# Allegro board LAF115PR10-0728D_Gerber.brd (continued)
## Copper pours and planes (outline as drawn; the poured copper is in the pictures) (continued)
HDMI_PLL_GND on BOTTOM (solid shape): 20.99,96.26 20.99,89.77 20.71,89.49 20.32,89.49 20.19,89.62 20.19,96.23 20.29,96.32 20.93,96.32
IR_GND on TOP (solid shape): 214.57,49.24 214.57,48.22 214.47,48.12 213.85,48.12 213.69,47.96 213.46,47.96 213.39,48.01 213.3,48.04 213.29,48.05 213.23,48.11 213.23,48.99 213.29,49.05 213.32,49.04 213.62,49.06 213.79,49.3 213.81,49.32 214.49,49.32
IR_GND on BOTTOM (solid shape): 213.23,49.02 213.65,49.02 213.89,48.78 213.89,48.18 213.66,47.95 213.46,47.95 213.31,48.04 213.12,48.05 212.89,48.28 211.87,48.28 211.81,48.34 211.81,49 211.91,49.11 213.14,49.11
LG1_CHG on BOTTOM (solid shape): 194.67,48.06 194.67,47.73 194.51,47.57 193.21,47.57 193.12,47.66 193.12,48.06 193.3,48.24 194.5,48.24
LG1_CHG on IN3 (solid shape): 202.29,44.13 202.29,43.76 201.93,43.39 201.6,43.39 201.25,43.66 200.91,43.39 199.98,43.39 199.83,43.54 199.83,44.03 200,44.19 200.23,44.19 201.25,44.19 201.32,44.25 202.17,44.25
LG1_VGA on TOP (solid shape): 85.49,128.62 85.49,127.83 85.35,127.69 84.29,127.69 84.24,127.74 84.24,128.53 84.24,128.67 84.36,128.8 85.32,128.8
LG1_VGA on TOP (solid shape): 76.74,129.2 77.34,129.2 77.44,129.1 77.45,129.1 78,129.1 78.12,128.97 78.12,128.72 78.04,128.63 77.77,128.63 77.53,128.88 77.39,128.88 77.28,128.99 76.34,128.99 76.28,129.06 76.28,129.14 76.33,129.2 76.74,129.2
LG1_VGA on BOTTOM (solid shape): 90.08,128.47 90.08,127.8 89.96,127.68 89.94,127.68 89.84,127.58 88.92,127.58 88.6,127.9 88.6,128.37 88.91,128.67 89.87,128.67
LG1_VGA on IN3 (solid shape): 89.91,128.54 89.91,127.73 89.78,127.6 83.55,127.6 83.42,127.73 83.42,128.61 83.57,128.76 89.7,128.76
LG2_CHG on BOTTOM (solid shape): 199.22,42.75 199.22,42.19 198.84,41.81 198.84,41.56 198.67,41.38 198.37,41.38 198.15,41.6 198.15,42.52 198.53,42.9 199.07,42.9
LG2_CHG on BOTTOM (solid shape): 203.69,44.16 203.69,43.42 202.93,42.67 202,42.67 201.9,42.77 201.9,43.08 202.03,43.21 203.16,43.21 203.22,43.26 203.25,43.26 203.41,43.42 203.41,43.45 203.46,43.5 203.46,44.13 203.53,44.21 203.64,44.21
LG2_CHG on IN3 (solid shape): 200.01,42.87 200.01,42.34 199.81,42.14 198.33,42.14 198.15,42.33 198.15,42.53 198.51,42.89 199.49,42.89 199.59,42.99 199.9,42.99
LG2_CHG on IN3 (solid shape): 203.11,43.07 203.11,42.76 202.56,42.21 201.27,42.21 201.18,42.3 201.18,42.9 201.23,42.95 201.25,42.95 201.32,42.95 201.39,42.97 201.74,42.97 201.95,43.18 203,43.18
LG2_VGA on TOP (solid shape): 89.89,132.2 89.89,131.29 89.84,131.24 88.86,131.24 88.72,131.38 88.72,132.08 88.91,132.27 89.82,132.27
LG2_VGA on TOP (solid shape): 77.68,130.22 78.02,130.22 78.02,130.22 78.14,130.1 78.14,129.89 78.02,129.77 77.74,129.77 77.42,130.09 77.39,130.09 77.29,130.2 76.34,130.2 76.28,130.26 76.28,130.35 76.34,130.4 77.49,130.4
LG2_VGA on BOTTOM (solid shape): 85.58,132.02 85.58,131.42 85.45,131.29 84.39,131.29 84.31,131.36 84.31,132.23 84.41,132.33 85.28,132.33
LG2_VGA on IN3 (solid shape): 90.1,132.2 90.1,131.39 89.9,131.19 83.5,131.19 83.35,131.34 83.35,132.24 83.5,132.39 89.91,132.39
LG2_VGA on IN3 (solid shape): 79.27,130.25 79.27,129.8 79.17,129.71 77.64,129.71 77.56,129.78 77.56,130.13 77.66,130.22 78.15,130.22 78.15,130.22 78.59,130.22 78.71,130.34 79.17,130.34
LG_1.2V on TOP (solid shape): 38.08,27.32 38.37,27.32 40.16,25.52 40.16,25.52 40.28,25.4 40.86,25.4 40.97,25.29 40.97,24.78 40.67,24.48 40.08,24.48 37.78,26.78 37.63,26.78 37.55,26.86 37.55,27.62 37.6,27.67 37.73,27.67
LG_VCCSA on BOTTOM (solid shape): 164.25,58.26 164.25,57.82 163.66,57.23 163,57.23 162.9,57.34 162.9,57.83 163.4,58.33 164.18,58.33
LX1_CHG on TOP (solid shape): 190.61,54.44 190.61,53.75 190.46,53.6 188.02,53.6 187.82,53.81 187.82,54.52 188.07,54.77 190.28,54.77
LX1_CHG on BOTTOM (solid shape): 193.52,51.32 197.9,51.32 198.03,51.19 198.03,48.65 197.9,48.52 191.93,48.52 189.44,51.01 185.94,51.01 185.83,51.11 185.83,54.62 186.15,54.94 189.9,54.94
LX1_CHG on BOTTOM (solid shape): 202.85,44.94 202.85,44.81 202.79,44.75 202.1,44.75 201.96,44.75 200.25,43.03 199.17,43.03 199.11,43.09 199.11,43.92 199.3,44.11 200.12,44.11 200.88,44.87 201.39,44.87 201.52,45 202.79,45
LX1_CHG on IN3 (solid shape): 200.86,44.89 201.24,44.89 201.37,44.76 201.37,44.48 201.2,44.32 200.29,44.32 199.98,44.62 199.98,44.94 200.24,45.19 200.55,45.19
LX1_VGA on TOP (solid shape): 97.85,127.21 97.85,126.02 97.32,125.49 94.59,125.49 94.36,125.26 93.98,125.26 93.97,125.24 93.87,125.24 92.57,123.93 90.17,123.93 89.47,124.63 85.16,124.63 85.02,124.77 85.02,127.25 85.12,127.35 94.95,127.35 95.83,128.23 96.83,128.23
LX1_VGA on TOP (solid shape): 77.34,128.75 77.47,128.75 77.72,128.5 78.09,128.5 78.09,128.51 78.38,128.51 78.52,128.65 79.03,128.65 79.09,128.58 79.09,128.07 78.96,127.95 77.82,127.95 77.79,127.96 77.66,128.1 77.66,128.3 77.4,128.56 77.34,128.56 77.3,128.6 76.34,128.6 76.28,128.66 76.28,128.75 76.34,128.8 77.29,128.8
LX1_VGA on BOTTOM (solid shape): 97.98,127.11 97.98,126.27 97.16,125.46 95.56,125.46 94.84,126.18 94.64,126.18 93.43,127.39 93.32,127.39 92.78,126.86 92.78,126.7 93.66,125.83 93.66,124.82 92.72,123.88 89.82,123.88 89.06,124.65 85.12,124.65 85.05,124.72 85.05,127.24 85.23,127.41 90.06,127.41 91.39,128.74 92.81,128.74 93.42,129.34 95.74,129.34
LX1_VGA on IN3 (solid shape): 89.73,125.86 89.73,125.14 89.57,124.98 88.65,124.98 88.49,125.14 88.49,125.72 88.65,125.88 89.15,125.88 89.31,126.04 89.55,126.04
LX2_CHG on TOP (solid shape): 192.46,45.17 192.46,43.05 192.28,42.87 191.15,42.87 190.95,43.07 190.95,45.1 191.13,45.29 192.34,45.29
LX2_CHG on BOTTOM (solid shape): 198.05,41.19 198.67,41.19 199.02,41.55 199.02,41.79 199.68,42.44 202.89,42.44 203.07,42.63 203.12,42.67 203.15,42.71 203.84,43.4 203.84,44.13 203.9,44.19 204.02,44.19 204.07,44.13 204.07,43.02 203.6,42.55 203.6,42.55 203.52,42.49 203.45,42.41 203.45,42.4 203.39,42.34 203.39,41.97 203.06,41.64 202.69,41.64 202.54,41.48 202.54,40.91 202.46,40.83 201.57,40.83 201.47,40.94 201.47,41.36 201.32,41.51 200.19,41.51 199.07,40.39 197.36,40.39 196.21,39.25 196.15,39.25 192.82,42.58 192.82,42.61 192.78,42.65 190.51,42.65 190.32,42.46 190.15,42.46 190,42.3 185.81,42.3 185.71,42.4 185.71,45.6 185.87,45.77 193.48,45.77
LX2_VGA on TOP (solid shape): 78.71,131.57 78.71,131.09 77.96,130.35 77.73,130.35 77.48,130.59 76.35,130.59 76.28,130.66 76.28,130.75 76.34,130.81 77.5,130.81 78.01,131.31 78.01,131.5 78.14,131.63 78.65,131.63
LX2_VGA on TOP (solid shape): 94.62,136.04 94.62,135.62 94.62,135.55 94.62,135.48 94.62,135.35 95.88,134.09 95.88,132.9 95.4,132.42 85.24,132.42 85.07,132.58 85.07,135.24 85.28,135.44 89.06,135.44 90.36,136.74 93.93,136.74
LX2_VGA on BOTTOM (solid shape): 94.56,136.08 94.56,135.61 93.85,134.89 93.71,134.89 93,134.18 93,134.04 93.48,133.56 93.66,133.56 94.75,134.65 95.26,134.65 95.82,134.09 95.82,133.64 93.75,131.57 90.85,131.57 89.9,132.52 85.16,132.52 85.09,132.6 85.09,135.31 85.28,135.5 88.67,135.5 88.68,135.52 89.05,135.52 90.38,136.85 93.79,136.85
LX2_VGA on IN3 (solid shape): 90.27,135.57 90.27,134.61 90.09,134.44 89.33,134.44 89.07,134.7 89.07,135.55 89.18,135.66 90.18,135.66
LX2_VGA on IN3 (solid shape): 79.01,131 79.01,130.86 78.5,130.35 77.68,130.35 77.59,130.45 77.59,130.73 77.75,130.89 78.16,130.89 78.51,131.24 78.77,131.24
LX_1.2V on TOP (solid shape): 49.69,30.16 49.69,28.63 49.54,28.48 46.97,28.48 46.74,28.71 46.74,29.85 47.18,30.28 49.56,30.28
LX_1.2V on TOP (solid shape): 39.07,27.82 39.1,27.82 39.26,27.78 39.43,27.82 39.48,27.82 39.57,27.91 40.13,27.91 40.22,27.82 40.22,26.83 40.99,26.06 40.99,25.76 40.83,25.6 40.64,25.6 38.54,27.69 38.16,27.69 37.96,27.9 37.96,28.06 38.01,28.11 38.78,28.11
LX_1.2V on BOTTOM (solid shape): 49.9,29.52 49.9,25.52 49.67,25.29 47.32,25.29 47.11,25.5 46.49,25.5 46.26,25.73 43.83,25.73 43.73,25.83 43.73,26.81 43.76,26.83 46.55,26.83 46.8,27.08 46.8,29.37 47.13,29.71 49.71,29.71
LX_1.8VALW on BOTTOM (solid shape): 165.6,45.89 165.6,44.97 165.99,44.57 167.42,44.57 167.52,44.48 167.52,43.85 167.43,43.77 166.62,43.77 165.89,43.05 165.84,43.02 165.79,43 162.46,43 162.21,43.24 162.21,45.73 163.16,46.67 164.81,46.67
LX_3V on BOTTOM (solid shape): 28.2,44.74 28.2,41.84 27.78,41.42 25.95,41.42 25.4,40.87 22.24,40.87 21,42.11 21,42.68 21.04,42.72 21.87,42.72 22.36,43.21 23.4,43.21 23.73,43.54 23.73,44.76 24.11,45.14 27.8,45.14
LX_5V on BOTTOM (solid shape): 23.02,101.51 23.02,99.02 23.03,99.01 23.03,98.87 23.66,98.24 24.38,98.24 24.49,98.13 24.94,98.13 25.02,98.04 25.02,97.98 24.54,97.49 21.16,97.49 21.04,97.61 17.5,97.61 17.42,97.68 17.42,101.71 17.88,102.17 22.36,102.17
LX_+1.35VGPU on TOP (solid shape): 149.11,110.5 149.11,109.04 148.95,108.89 147.28,108.89 147.2,108.96 147.2,110.57 147.3,110.68 148.93,110.68
LX_+1.35VGPU on BOTTOM (solid shape): 149.09,111.36 149.09,108.16 148.27,107.34 143.86,107.34 143.73,107.46 143.73,108.48 143.86,108.61 145.63,108.61 146.2,109.17 146.2,111.51 146.34,111.65 148.8,111.65
LX_+1VALW on TOP (solid shape): 160.56,51.24 160.56,50.03 160.73,49.86 161.41,49.86 161.44,49.83 161.44,49.33 161.39,49.27 160.24,49.27 159.86,49.65 159.86,51.23 160.05,51.42 160.38,51.42
LX_+1VALW on BOTTOM (solid shape): outline of 87 points within 156.83,48.05 161.98,53.45
LX_VCCSA on TOP (solid shape): 157.76,61.46 157.76,59.85 157.59,59.67 155,59.67 154.88,59.8 154.88,62.03 154.97,62.12 157.1,62.12
LX_VCCSA on BOTTOM (solid shape): 157.81,61.55 157.81,60.13 158.06,59.88 160.64,59.88 161.1,59.41 164.2,59.41 164.26,59.35 164.26,59.11 164.2,59.05 163.36,59.05 163.2,58.9 161.09,58.9 161,58.8 158.09,58.8 157.1,57.81 154.75,57.81 154.66,57.91 154.66,58.99 154.66,59 154.66,59.25 155.59,59.25 155.59,60.01 154.66,60.01 154.66,61.65 154.7,61.7 157.65,61.7
LX_VCORE1 on BOTTOM (solid shape): 161.74,66.97 161.74,65.76 161.93,65.57 165.64,65.57 165.69,65.52 165.69,64.82 165.67,64.8 159.76,64.8 158.13,63.18 155.62,63.18 155.01,63.8 155.01,66.08 155.13,66.21 156.34,66.21 156.4,66.15 156.4,65.26 156.47,65.19 157.23,65.19 157.29,65.26 157.29,66.15 158.18,67.03 161.67,67.03
LX_VCORE2 on TOP (solid shape): 158.19,88.79 158.19,87.21 158.09,87.1 155.39,87.1 155.13,87.35 155.13,88.72 155.31,88.89 158.09,88.89
LX_VCORE2 on BOTTOM (solid shape): 161.16,88.62 163.77,88.62 163.9,88.5 163.9,87.86 163.83,87.8 162.56,87.8 162.43,87.67 162.43,83.93 162.31,83.8 160.56,83.8 159.91,84.45 158.54,84.45 158.05,84.94 158.05,87.61 157.99,87.67 157.23,87.67 157.16,87.61 157.16,86.72 157.1,86.66 155.83,86.66 155.13,87.35 155.13,88.62 155.64,89.13 160.66,89.13
LX_VGT1 on TOP (solid shape): 152.33,93.52 152.33,93.09 152.66,92.77 152.66,90.85 152.54,90.73 151.6,90.73 151.39,90.95 151.39,93.46 151.68,93.76 152.09,93.76
LX_VGT1 on BOTTOM (solid shape): 152.28,93.4 152.28,92.2 153.1,92.2 153.1,93.37 153.39,93.66 154.85,93.66 156.2,92.31 157.48,92.31 157.55,92.24 157.55,90.97 157.74,90.78 161.46,90.78 161.53,90.71 161.53,90.05 161.43,89.96 151,89.96 150.12,90.85 150.12,93.24 150.58,93.71 150.59,93.71 150.62,93.75 151.93,93.75
PHASE_VGT1 on BOTTOM (solid shape): 161.74,96.75 161.74,95.93 161.67,95.86 161.25,95.86 161,95.6 161,95.01 160.91,94.92 160.78,94.92 160.66,95.04 160.66,95.94 160.85,96.13 160.85,96.75 160.91,96.82 161.67,96.82
POK on BOTTOM (solid shape): 100.18,31.24 100.18,30.2 100.47,29.9 100.55,29.9 100.63,29.89 100.72,29.9 100.83,29.9 100.97,30.04 100.97,30.23 101.07,30.33 101.37,30.33 101.44,30.26 101.44,30.07 101.46,30.06 101.46,29.62 101.81,29.27 101.81,28.15 101.74,28.08 100.37,28.08 100.27,28.18 100.27,29.53 99.78,30.02 99.78,31.25 99.86,31.34 100.08,31.34
POWER_SW#_MB on TOP (solid shape): 31.75,65.46 31.75,63.73 32.13,63.35 32.13,62.2 31.86,61.92 31.5,61.72 31.52,61.34 31.55,61.3 31.5,61.26 30.72,61.26 30.49,61.48 29.06,61.48 28.64,61.9 28.64,64.57 28.73,64.66 29.49,64.66 29.49,64.45 30.33,64.45 30.41,64.36 30.41,64.05 30.62,63.84 30.92,63.84 31.12,64.05 31.12,64.1 31.14,64.12 31.14,65.51 31.15,65.51 31.7,65.51
REGOUT on TOP (solid shape): 21.08,86.1 22.04,86.1 22.12,86.02 22.13,86.02 22.41,85.74 22.41,84.98 22.64,84.75 22.83,84.75 22.9,84.68 22.9,83.97 22.83,83.9 22.66,83.9 22.59,83.97 21.28,83.97 21.13,84.12 21.13,84.14 21.02,84.4 20.77,84.5 20.75,84.5 20.7,84.55 20.7,84.57 20.59,84.82 20.35,84.92 20.33,84.92 20.05,85.2 20.06,85.23 20.09,85.32 20.1,85.41 20.06,85.56 19.96,85.67 19.96,85.99 20.11,86.14 21.04,86.14
RING2 on TOP (solid shape): 27.26,20.99 27.26,19.34 28.07,18.53 28.07,17.38 27.44,16.75 27.44,15.92 27.37,15.85 27.29,15.85 27.23,15.91 27.23,17.07 27.41,17.25 27.41,17.36 27.41,17.42 27.4,17.47 27.4,18.24 26.58,19.06 26.58,20.91 26.7,21.04 27.21,21.04
RING2_R on TOP (solid shape): 17.76,11.03 17.76,10.8 16.85,9.89 16.85,7.93 16.57,7.65 15.99,7.65 15.73,7.91 15.73,8.34 15.82,8.43 15.82,10.46 16.52,11.16 17.64,11.16
RING2_R on TOP (solid shape): 26.55,23.3 27.98,23.3 28.13,23.15 28.13,21.75 27.75,21.37 26.62,21.37 26.58,21.41 26.58,22.21 26.34,22.45 26.12,22.45 25.99,22.58 25.99,23.38 26.09,23.48 26.37,23.48
RING2_R on IN1 (solid shape): 16.82,8.14 16.82,7.81 16.29,7.28 14.79,7.28 14.72,7.35 14.72,7.81 15.31,8.4 16.56,8.4
RING2_R on IN2 (solid shape): 16.82,8.14 16.82,7.81 16.29,7.27 14.79,7.27 14.72,7.35 14.72,7.81 15.31,8.4 16.56,8.4
RING2_R on IN3 (solid shape): 17.74,11.03 17.74,10.32 17.59,10.17 16.11,10.17 15.71,10.57 15.71,11.06 15.83,11.18 17.59,11.18
RING2_R on IN3 (solid shape): 26.54,23.38 26.54,22.53 26.45,22.44 25.22,22.44 24.62,23.03 24.62,23.74 24.89,24.01 25.9,24.01
SLEEVE on TOP (solid shape): 26.4,20.89 26.4,19.29 26.41,19.27 26.41,18.9 27.24,18.07 27.24,17.36 27.04,17.16 27.04,15.92 26.97,15.85 26.9,15.85 26.83,15.92 26.83,17.22 26.68,17.37 26.68,17.61 25.66,18.63 25.66,20.91 25.74,20.99 26.3,20.99
SLEEVE_R on TOP (solid shape): 19.01,11.11 19.01,10.42 18.7,10.12 18.7,7.86 17.74,7.86 17.68,7.91 17.68,9.54 17.74,9.6 17.74,10.54 17.9,10.7 17.9,11.01 18.18,11.29 18.83,11.29
SLEEVE_R on TOP (solid shape): 24.75,22.22 26.21,22.22 26.3,22.13 26.3,21.41 26.17,21.28 25.62,21.28 25.51,21.17 25.51,20.79 25.36,20.63 24.8,20.63 24.72,20.71 24.72,21.05 24.61,21.17 24.38,21.17 24.17,21.37 24.17,22.16 24.36,22.35 24.63,22.35
SLEEVE_R on IN1 (solid shape): 18.7,8.52 18.7,7.91 18.6,7.81 17.84,7.81 16.93,8.72 16.93,8.97 17.33,9.38 17.84,9.38
SLEEVE_R on IN3 (solid shape): 24.74,22.22 24.74,21.39 24.57,21.23 23.9,21.23 22.88,22.25 22.88,22.65 23.11,22.88 24.08,22.88
SLEEVE_R on IN3 (solid shape): 19.03,11.87 19.03,10.6 18.93,10.5 18.14,10.5 17.9,10.74 17.9,11.91 18.22,12.23 18.68,12.23
SNB_VCCSA on TOP (solid shape): 157.84,59.36 157.84,58.58 157.39,58.13 154.93,58.13 154.84,58.21 154.84,59.33 154.94,59.43 157.77,59.43
SNUB1_CHG on TOP (solid shape): 190.05,51.85 190.05,51.04 189.9,50.88 186.77,50.88 186.6,51.06 186.6,51.95 186.7,52.05 189.85,52.05
SNUB2_CHG on TOP (solid shape): 190.74,46.61 190.74,45.63 189.87,44.76 189.87,43.65 189.76,43.53 188.69,43.53 188.6,43.62 188.6,45.32 188.72,45.44 189.3,45.44 189.56,45.69 189.56,46.55 189.71,46.71 190.65,46.71
SNUB_+1.35VGPU on TOP (solid shape): 151.01,111.34 151.01,108.96 150.97,108.92 150.01,108.92 149.87,109.06 149.87,110.4 149.34,110.93 149.34,111.56 149.36,111.59 150.76,111.59
SNUB_+1VALW on TOP (solid shape): 159.29,50.8 159.29,49.84 159.17,49.72 158.72,49.72 158.49,49.48 158.49,48.55 158.44,48.51 157.83,48.51 157.77,48.57 157.77,49.55 157.48,49.84 157.48,50.76 157.58,50.86 159.23,50.86
UG1_CHG on BOTTOM (solid shape): 194.66,54.4 194.66,53.45 194.47,53.25 193.77,53.25 193.58,53.45 193.58,54.4 193.71,54.52 194.53,54.52
UG1_CHG on IN3 (solid shape): 201.11,46.1 201.11,45.8 201.33,45.59 201.33,45.19 201.18,45.04 200.89,45.04 200.61,45.32 200.59,45.32 200.34,45.58 200.34,46.11 200.52,46.29 200.92,46.29
UG1_VGA on TOP (solid shape): 85.52,122.78 85.52,122.22 85.36,122.06 85.05,122.06 84.72,122.4 83.97,122.4 83.8,122.56 83.8,123.22 83.88,123.3 85,123.3
UG1_VGA on TOP (solid shape): 77.53,128.24 77.53,128.05 77.75,127.82 77.8,127.82 77.89,127.73 77.89,127.51 77.78,127.4 77.53,127.4 77.34,127.59 77.34,128.01 77.15,128.2 76.34,128.2 76.28,128.26 76.28,128.35 76.33,128.41 77.36,128.41
UG1_VGA on BOTTOM (solid shape): 90.61,123.02 90.61,122.47 90.49,122.35 89.41,122.35 89.12,122.06 88.79,122.06 88.64,122.21 88.64,122.77 89.02,123.15 90.48,123.15
UG1_VGA on IN3 (solid shape): 90.53,123.43 90.53,122.74 90.41,122.61 89.49,122.61 89.33,122.78 89.33,123.67 89.54,123.88 90.08,123.88
UG1_VGA on IN3 (solid shape): 86.04,123.4 86.04,123.19 85.24,122.39 83.25,122.39 83,122.64 83,122.88 83.4,123.27 85.09,123.27 85.42,123.6 85.84,123.6
UG1_VGA on IN3 (solid shape): 77.74,127.81 77.82,127.81 78.39,127.24 78.39,126.88 78.14,126.63 77.82,126.63 77.57,126.87 77.57,127.29 77.42,127.44 77.42,127.72 77.56,127.86 77.7,127.86
UG2_CHG on BOTTOM (solid shape): 200.99,41.21 200.99,40.79 199.87,39.67 199.87,39.67 199.6,39.4 198.32,39.4 196.16,37.24 194.35,37.24 194.17,37.43 194.17,37.87 194.22,37.92 195.62,37.92 197.87,40.18 199.1,40.18 200.27,41.34 200.86,41.34
UG2_CHG on BOTTOM (solid shape): 204.46,44.12 204.46,42.87 204.44,42.85 204.44,42.47 204.4,42.41 204.37,42.34 204.37,42.33 204,41.96 203.59,41.96 203.52,42.03 203.52,42.29 204.2,42.96 204.2,43.35 204.26,43.42 204.26,44.14 204.31,44.18 204.4,44.18
UG2_CHG on IN3 (solid shape): 204.51,42.74 204.51,42.53 203.39,41.4 203.23,41.4 202.87,41.76 202.87,42.03 203.75,42.91 204.34,42.91
UG2_CHG on IN3 (solid shape): 201.88,41.73 201.88,41.1 201.83,41.05 201,41.05 200.66,40.71 200.06,40.71 199.92,40.85 199.92,41.23 200.51,41.82 201.79,41.82
UG2_VGA on TOP (solid shape): 90.05,137.93 90.05,136.69 89.91,136.55 88.79,136.55 88.69,136.64 88.69,137.88 88.91,138.1 89.89,138.1
UG2_VGA on TOP (solid shape): 77.8,131.81 77.8,131.53 77.8,131.37 77.43,131 76.34,131 76.28,131.06 76.28,131.14 76.35,131.2 77.14,131.2 77.33,131.39 77.33,131.8 77.46,131.93 77.68,131.93
UG2_VGA on BOTTOM (solid shape): 85.56,137.71 85.56,136.86 85.43,136.74 84.25,136.74 84.04,136.94 84.04,137.74 84.2,137.89 85.38,137.89
UG2_VGA on IN3 (solid shape): 89.99,137.52 89.99,136.63 89.85,136.49 83.4,136.49 83.23,136.66 83.23,137.59 83.46,137.82 89.69,137.82
UG_1.2V on IN1 (solid shape): 39.35,28.52 39.35,28.51 39.37,28.48 39.45,28.32 39.57,28.17 39.57,27.74 39.43,27.61 38.44,27.61 38.3,27.74 38.3,28.56 38.46,28.72 39.15,28.72
UG_VCCSA on BOTTOM (solid shape): 164.26,60.19 164.26,59.63 164.19,59.56 164.08,59.56 164.08,59.56 162.93,59.56 162.8,59.69 162.8,60.14 162.94,60.28 164.17,60.28
USB20_VCCB on TOP (solid shape): 202.4,38.59 202.4,37.34 203.28,36.46 203.28,36.24 202.66,35.62 202.66,34.63 202.68,34.61 202.68,34.59 202.88,34.4 202.88,33.95 204.04,32.79 204.04,32.45 203.84,32.25 203.28,32.25 202.33,31.3 200.82,31.3 200.41,31.71 200.41,38.06 201.16,38.81 202.18,38.81
USB20_VCCB on BOTTOM (solid shape): 202.33,38.57 202.33,37.96 201.57,37.21 201.57,35.65 201.34,35.42 200.64,35.42 200.48,35.58 200.48,35.83 200.2,36.11 198.04,36.11 197.82,36.33 197.82,38.22 198.18,38.58 199.4,38.58 199.47,38.52 199.68,38.25 200.02,38.29 200.2,38.29 200.57,38.26 200.76,38.58 200.95,38.58 201.09,38.72 202.18,38.72
USB30_VCCA on TOP (solid shape): 17.91,55.62 18.17,55.37 18.27,55.37 18.43,55.21 18.72,55.21 18.76,55.18 19.13,55.18 19.16,55.21 19.54,55.21 19.54,55.21 19.86,55.21 20.02,55.05 20.02,54.24 19.95,54.17 16.85,54.17 16.73,54.28 16.73,55.51 16.86,55.63 17.91,55.63
USB30_VCCA on TOP (solid shape): 31.29,51.56 32.3,51.56 32.48,51.38 32.48,50.51 32.59,50.4 32.59,49.81 32.65,49.75 32.65,49.59 32.58,49.52 32.22,49.52 32.14,49.6 30.81,49.6 30.65,49.68 30.48,49.68 30.47,49.67 30.24,49.67 30.14,49.78 30.14,51.46 30.31,51.63 31.22,51.63
USB30_VCCA on BOTTOM (solid shape): outline of 82 points within 15.34,54.22 23.02,61.03
USB30_VCCA on IN1 (solid shape): 17.84,56.89 17.84,55.67 18.16,55.34 18.16,54.48 17.98,54.3 16.86,54.3 15.54,55.61 15.26,55.89 15.26,57.26 15.44,57.44 17.29,57.44
USB30_VCCA on IN3 (solid shape): outline of 508 points within 16.86,49.85 32.35,56.38
USB30_VCCC on TOP (solid shape): outline of 190 points within 14.58,38.08 19.39,52.38
USB30_VCCC on BOTTOM (solid shape): 20.02,57.41 20.02,56.86 20.02,56.86 20.56,56.86 20.57,56.86 20.57,57.41 20.57,57.41 20.82,57.41 20.82,57.41 20.82,56.86 20.82,56.86 21.36,56.86 21.45,56.78 21.45,55.61 21.32,55.49 20.78,55.49 20.35,55.06 20.35,53.32 20.17,53.14 19.78,53.14 19.39,52.75 19.39,51.59 19.27,51.47 19.1,51.47 19.09,51.48 17.95,51.48 17.84,51.59 17.84,51.97 18.3,52.42 18.3,55.4 18.31,55.43 18.35,55.45 18.45,55.46 18.55,55.51 18.63,55.53 18.7,55.48 19.36,55.58 18.8,55.95 18.72,55.93 18.66,55.98 18.62,56.03 18.6,56.1 18.62,56.16 18.7,56.41 18.59,56.65 18.56,56.72 18.59,56.79 18.66,56.86 19.76,56.86 19.76,56.87 19.76,57.41 19.77,57.41 20.02,57.41
USB30_VCCC on IN1 (solid shape): 19.19,39.67 19.19,38.82 19.19,32.57 18.86,32.24 15.62,32.24 15.31,32.55 15.31,35.16 15.59,35.44 16.98,35.44 17.07,35.54 17.09,35.54 17.43,35.85 17.36,36.3 17.46,36.6 17.36,36.89 17.46,37.18 17.36,37.47 17.46,37.77 17.36,38.06 17.31,38.7 16.67,38.72 16.09,38.75 15.91,38.2 15.89,38.11 15.81,38.07 15.1,38.07 14.49,38.68 14.49,39.59 14.96,40.06 18.79,40.06
USBC_B2B_S1 on TOP (solid shape): 49.67,124.02 49.67,122.7 49.1,122.14 49.1,120.59 48.28,119.77 48.28,119.77 48.18,119.67 47.03,119.67 46.87,119.73 46.71,119.71 46.63,119.72 46.55,119.7 46.52,119.69 45.59,120.62 44.65,120.62 44.46,120.81 44.46,122.31 44.62,122.47 48.04,122.47 48.4,122.83 48.4,124.06 48.65,124.32 49.37,124.32
USBC_B2B_S2 on TOP (solid shape): 58.52,129.19 58.52,127.04 58.35,126.87 57.09,126.87 56.85,127.11 56.85,127.61 56.61,127.85 56.19,127.85 56.09,127.95 56.09,128.63 56.12,128.66 57.74,128.66 57.88,128.79 57.88,129.1 58.02,129.25 58.46,129.25
VCREF0 on TOP (solid shape): 47.07,68.63 47.07,66.79 47.58,66.28 47.58,65.79 47.63,65.75 47.63,65.64 47.83,65.44 47.83,65.23 48.01,65.04 49.62,65.04 49.71,64.95 49.71,64.54 49.65,64.47 47.36,64.47 47.32,64.51 47.32,65.02 47.14,65.21 47.14,66.02 47.14,66.03 47.17,66.3 47,66.51 46.85,66.66 46.85,68.6 46.92,68.67 47.03,68.67
N20135074 on TOP (solid shape): 92.79,128.57 92.79,127.73 92.71,127.64 90.17,127.64 90.09,127.72 90.09,128.6 90.18,128.68 92.68,128.68
N20135091 on TOP (solid shape): 80.17,128.39 80.17,126.8 80.11,126.74 79.47,126.74 79.41,126.8 79.41,128.65 79.92,128.65
N20135197 on TOP (solid shape): 92.79,132.16 92.79,131.3 92.72,131.22 90.12,131.22 90.09,131.25 90.09,132.27 90.11,132.29 92.67,132.29
N20135212 on TOP (solid shape): 78.9,134.17 78.9,132.14 78.77,132.01 78.11,132.01 78.08,132.04 78.08,132.63 78.13,132.67 78.13,133.35 78.14,133.35 78.14,134.23 78.18,134.27 78.8,134.27
N20135251 on TOP (solid shape): 73.52,133.9 73.52,133.41 74.08,132.85 74.08,131.86 74.01,131.8 73.15,131.8 73.06,131.88 73.06,132.95 72.84,133.17 72.84,133.89 72.93,133.98 73.44,133.98
N20135264 on TOP (solid shape): 75.08,133.99 75.08,133.47 75.1,133.45 75.1,133.36 75.19,133.36 75.66,132.89 75.66,131.88 75.6,131.82 75.15,131.82 75.09,131.88 75.09,132.61 74.98,132.72 74.98,132.74 74.41,133.32 74.41,133.97 74.49,134.06 75.01,134.06
N21269026 on TOP (solid shape): 161.77,88.73 161.77,87.26 161.61,87.1 159.72,87.1 159.63,87.19 159.63,88.78 159.73,88.88 161.62,88.88
N21273981 on TOP (solid shape): 155.39,92.46 155.39,91.48 155.55,91.32 156.52,91.32 156.64,91.2 156.64,90.44 156.44,90.24 154.37,90.24 154.21,90.4 154.21,92.44 154.36,92.58 155.26,92.58
N21379353 on BOTTOM (solid shape): 24.5,96.74 24.5,96.23 24.26,95.99 24.26,95.64 24.13,95.51 23.83,95.51 23.72,95.62 23.72,95.84 23.53,96.03 23.53,96.78 23.62,96.86 24.37,96.86
N21484820 on TOP (solid shape): 172.53,44.64 172.53,43.65 172,43.12 172,41.33 171.69,41.02 170.43,41.02 170.23,41.22 170.23,43.79 170.61,44.17 170.61,44.65 170.76,44.8 172.36,44.8
N21484820 on BOTTOM (solid shape): 174.16,45.26 174.16,44.65 173.93,44.41 173.54,44.41 173.25,44.12 173.25,44.04 173.07,43.86 173.07,41.7 172.96,41.59 169.9,41.59 169.71,41.78 169.71,44.45 169.77,44.51 170.79,44.51 171.61,45.33 174.09,45.33
N22328258 on TOP (solid shape): 73.78,145.5 73.78,144.98 74.29,144.98 74.29,145.48 74.3,145.5 74.56,145.5 74.58,145.48 74.58,144.98 75.69,144.98 75.81,144.85 75.81,141.79 75.59,141.56 72.29,141.56 72.12,141.73 72.12,142.74 72.12,142.8 72.12,144.87 72.23,144.98 73.49,144.98 73.49,144.98 73.49,145.47 73.53,145.51 73.77,145.51
N22328258 on BOTTOM (solid shape): outline of 84 points within 71.96,141.09 77.95,146.55
N24263922 on TOP (solid shape): 41.68,129.29 41.68,128.49 42.12,128.05 42.12,127.59 41.94,127.41 41.42,127.41 41.18,127.17 40.82,127.21 40.61,126.91 40.58,126.84 40.51,126.81 40.4,126.81 40.4,128.52 39.85,129.07 39.85,129.46 39.85,129.47 39.85,129.69 40.01,129.85 41.12,129.85
N24460612 on TOP (solid shape): 85.94,114.82 85.94,114.1 85.83,114 84.43,114 83.87,113.43 82.81,113.43 82.72,113.52 82.72,114.21 83.45,114.93 85.82,114.93
N24468099 on TOP (solid shape): outline of 96 points within 18.31,130.21 22.24,132.84
N40598435 on BOTTOM (solid shape): 23.68,40.62 23.68,40.22 23.61,40.14 22.89,40.14 22.69,39.94 22.69,39.53 22.64,39.48 22.06,39.48 21.99,39.54 21.99,40.56 22.16,40.72 23.58,40.72
N40598500 on BOTTOM (solid shape): 23.99,102.73 23.99,102.19 24.23,101.94 24.23,101.28 24.16,101.21 23.25,101.21 23.15,101.32 23.15,101.66 22.77,102.04 22.77,102.47 23.1,102.8 23.91,102.8
N42785908 on BOTTOM (solid shape): 204.24,58.86 204.24,57.58 204.26,57.56 204.26,57.11 204.31,57.07 204.31,57 204.38,57 204.84,56.53 204.84,55.85 204.84,55.85 204.84,53.53 204.63,53.32 203.82,53.32 203.3,52.8 203.3,51.48 203.17,51.35 201.65,51.35 201.58,51.41 201.58,52.3 201.9,52.62 202.09,52.62 203.02,53.55 203.02,58.13 202.57,58.59 202.57,59.03 203.14,59.6 203.49,59.6
N42787460 on BOTTOM (solid shape): 199.81,46.57 199.81,45.56 200.05,45.32 200.05,44.57 199.96,44.49 199.17,44.49 199.09,44.57 199.09,46.58 199.13,46.63 199.75,46.63
N45789065 on TOP (solid shape): 160.36,66.61 160.36,64.07 160.23,63.94 158.96,63.94 158.77,64.13 158.77,66.61 158.96,66.8 160.17,66.8
N47714748 on TOP (solid shape): 52.25,30.23 52.25,27.67 52.23,27.65 51.7,27.65 51.66,27.69 51.66,28.35 51.49,28.52 51.25,28.52 51.19,28.58 51.19,30.24 51.21,30.26 52.22,30.26
N47719295 on TOP (solid shape): 36.55,27.65 36.55,26.39 37.32,25.63 37.32,25 37.3,24.98 35.03,24.98 35.02,24.99 35.02,25.6 35.07,25.65 35.21,25.65 36.34,26.78 36.34,27.64 36.41,27.71 36.49,27.71
N47887852 on TOP (solid shape): 166.37,43.93 166.37,43.11 166.32,43.06 165.85,43.06 165.77,42.98 165.22,42.98 165.21,42.99 164.85,42.99 164.85,42.98 164.63,42.98 164.63,42.99 164.27,42.99 164.26,42.98 163.66,42.98 163.66,43.94 163.77,44.05 166.26,44.05

Small or netless copper shapes (teardrops, artwork), in the pictures only: 277 on TOP, 33 on BOTTOM, 4 on IN1, 3 on IN3

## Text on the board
User.Comments: LAF115P | 2018-07-28 | CAL50/DAL10 | 2017-07-28 | Moopi
Ref Des/Silkscreen Top: A
User.38: trace Width | Width/space | L1-TOP | L2-GND1 | L3-IN1 | L4-VCC | L5-IN2 | L6-IN3 | L7-GND2 | L8-BOT | 7.2mil | 7.4mil | 5.5mil | 5.8mil | 4.9mil | 4.4mil | 4.7mll | 5.3mil | 5.4 / 4.5 | 4.8 / 3.9 | 5.1 / 3.5 | 4.3/3.5 | 4.9/3.5 | 4.4 / 4.3 | 4.7 / 3.9 | 5.3 / 4.2 | 3.5 / 6.4 | 3.5 / 4.1 | L2/L4 | L4/L7 | L2 | L7 | 5.6mil | 4.6mil | 5.2/3.5 | 4.6/3.7 | L5/L7 | 1_0mm-8L_160824 | LAYER | NAME | STACKUP: 8 LAYER | 39 ohm | 45 ohm | THICKNESS=1.0mm | 50 ohm | 80 ohm | 82 ohm | 85 ohm | 100 ohm | Ref
User.39: FIGURE | SIZE | 8.0 | 22.0 | 28.0 | 35.0 | 118.0 | 126.0 | 130.0 | 138.0 | 146.0 | 157.0 | 197.0 | 43.0 | 63.0 | 220.0 | 51.0x28.0 | 55.0x24.0 | 63.0x24.0 | 63.0x35.0 | 67.0x28.0 | 71.0x31.0 | 75.0x28.0 | 102.0x31.0 | 157.0x118.0 | 157.0x146.0 | 33.0x28.0 | DRILL CHART: TOP to BOTTOM | ALL UNITS ARE IN MILS | TOLERANCE | +3.0/-3.0 | +2.0/-2.0 | +0.0/-0.0 | PLATED | NON-PLATED | QTY | 6953 | 19 | 18 | 8 | 5 | 2 | 1 | 4 | 7
